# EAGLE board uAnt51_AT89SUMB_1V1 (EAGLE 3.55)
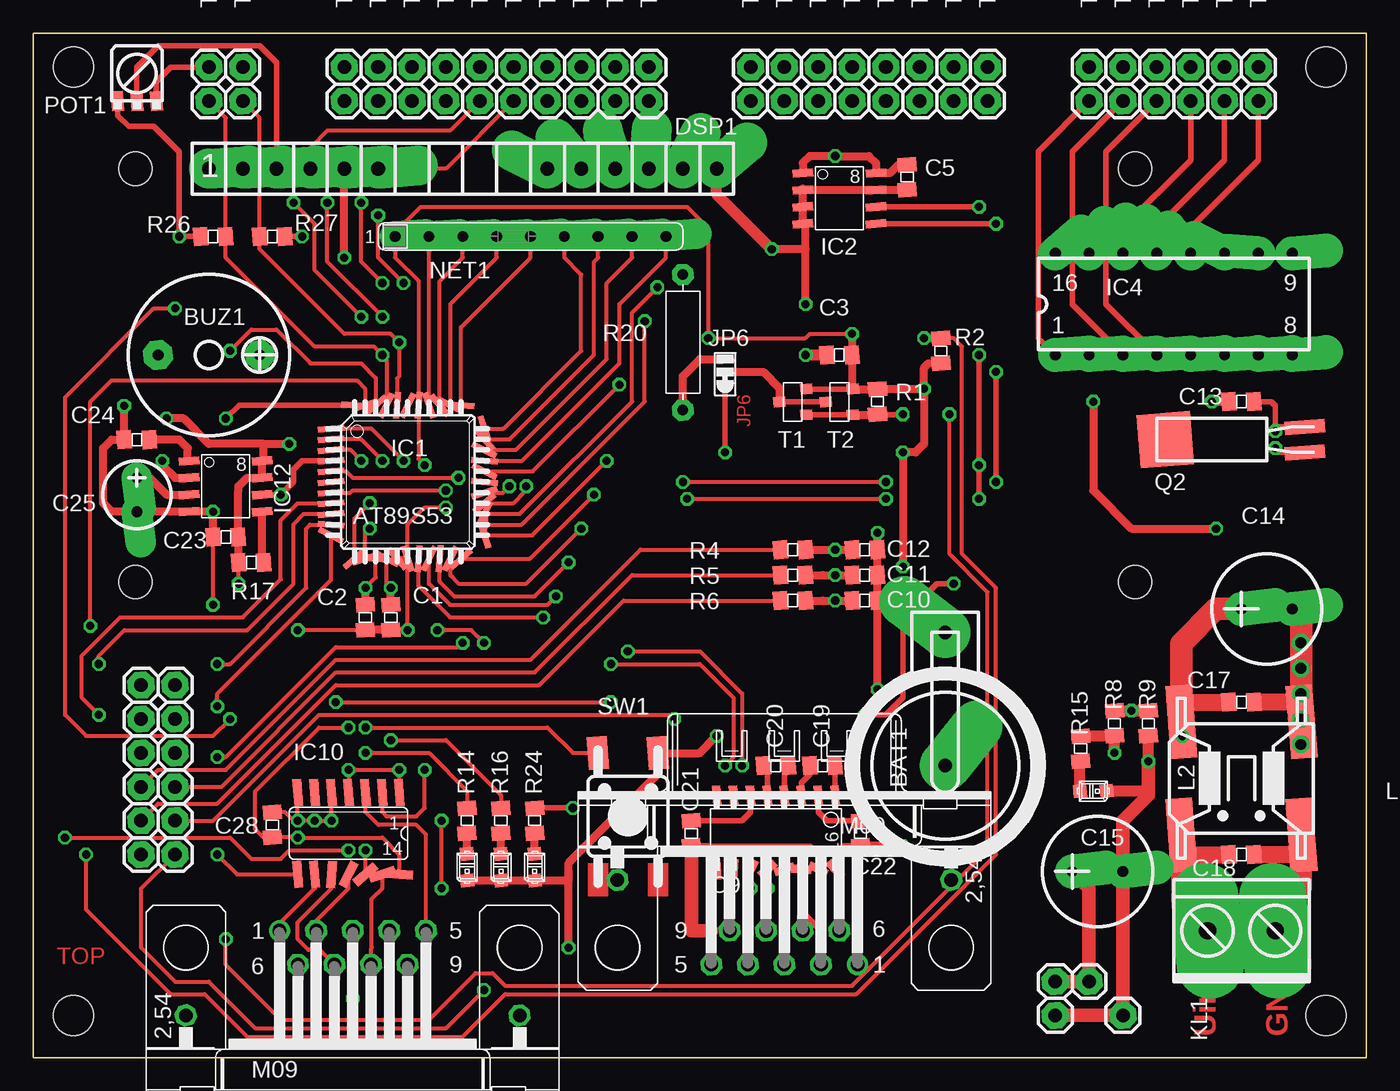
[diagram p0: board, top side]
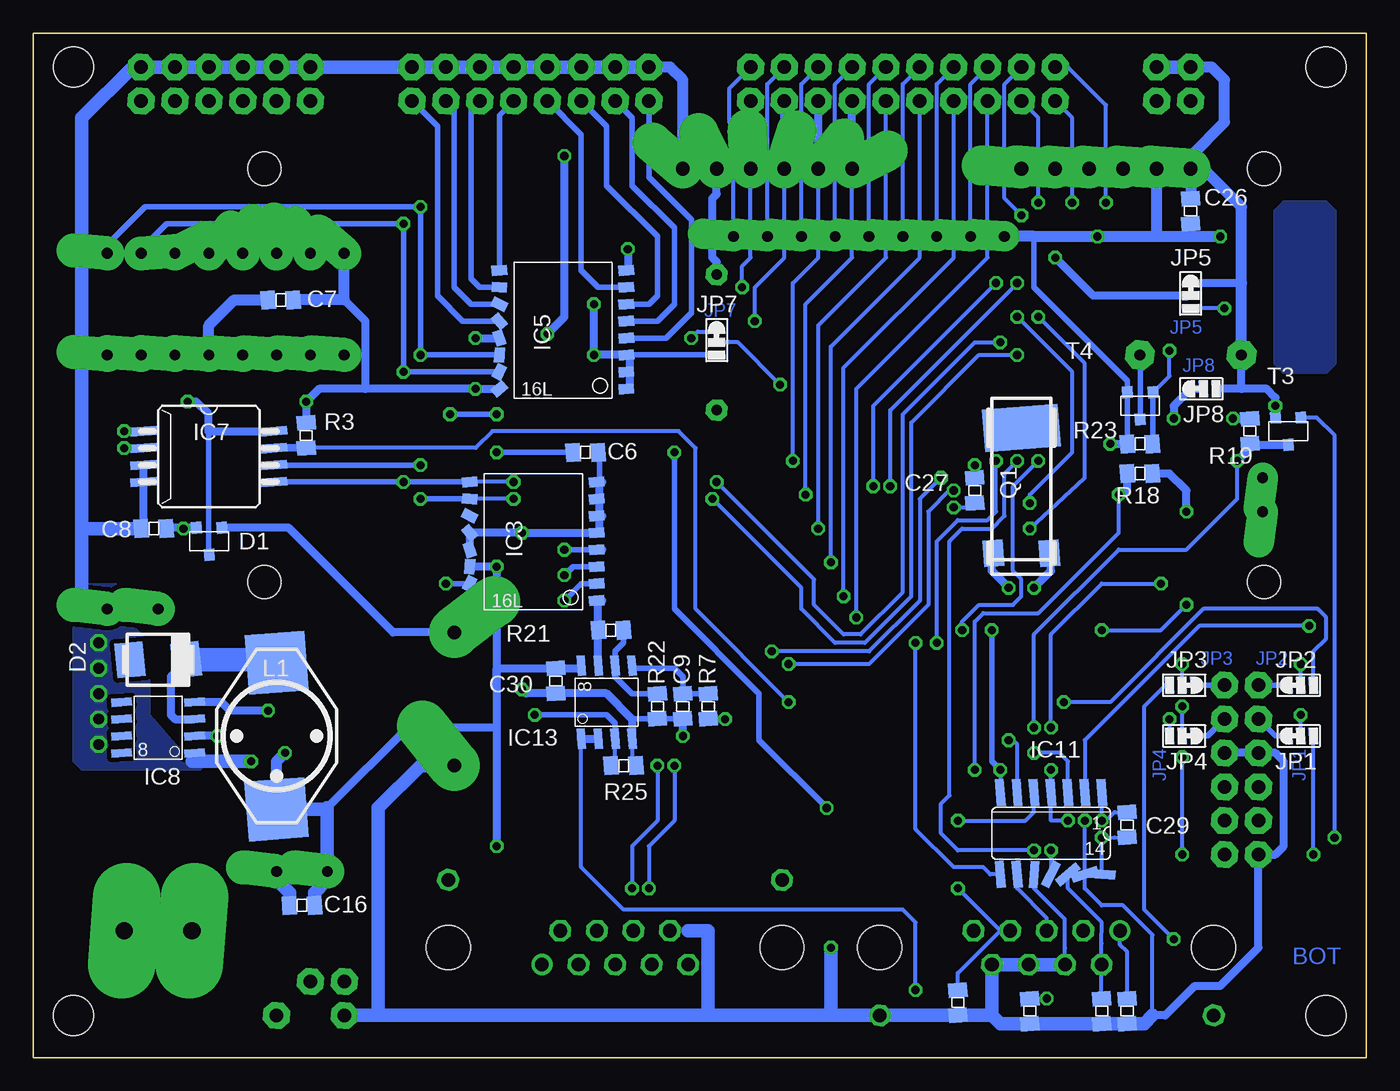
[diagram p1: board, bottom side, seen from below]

Size 100 x 76.81 mm. Coordinates in mm from the lower left corner, seen from the top.
Outline: 0,76.81 0,0 100,0 100,76.81 0,76.81
Copper layers used: Top, Bottom
Holes 3 mm at 96.99,3.16 3.01,3.16 3.01,74.28 96.99,74.28

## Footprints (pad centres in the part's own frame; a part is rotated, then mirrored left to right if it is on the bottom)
YST50X = drill 1.016 pad 3.81 offset: TT 10,0;  0,0
UCW06 = drill 0.813 pad 2.184 octagon:  0,-3.81;  0,3.81
05 = smd 1.092 x 1.397 rotated 4.4:  0.94,0 | smd 1.092 x 1.397 rotated 4.3:  -0.94,0
KO3_8 = drill 0.813 pad 2.54 offset:  -1.905,0;  1.905,0
KO2_5 = drill 0.813 pad 2.3 offset:  -1.27,0;  1.27,0
9H = drill 1.016 pad 1.6 octagon:  5.486,1.27;  2.743,1.27;  0,1.27;  -2.743,1.27;  4.115,-1.27;  1.372,-1.27;  -1.372,-1.27;  -4.115,-1.27;  12.522,-5.08;  -12.522,-5.08 | drill 1.016 pad 1.6 round:  -5.486,1.27 | hole 3.302: 12.522,0; -12.522,0
T23 = smd 0.787 x 0.889 rotated 4.4:  0.991,1.016 | smd 0.787 x 0.889 rotated 4.3:  -0.94,1.016 | smd 0.787 x 0.889 rotated 4.5:  0.025,-1.016
B = smd 2.1 x 2.6 rotated 6.6:  -2.1,0 | smd 2.1 x 2.6 rotated 5.7:  2.1,0
0524B = drill 1.016 pad 3 offset:  0,0;  2.54,0;  5.08,0;  7.62,0;  10.16,0;  12.7,0;  25.4,0;  27.94,0;  30.48,0;  33.02,0;  35.56,0;  38.1,0 | hole 2.5: -5.5,-31; -5.5,0; 69.5,0; 69.5,-31
FP44 = smd 0.45 x 2 rotated 26.8:  4,-5.75 | smd 0.45 x 2 rotated 4.3:  3.2,-5.75;  -4,-5.75 | smd 0.45 x 2 rotated 5:  2.4,-5.75 | smd 0.45 x 2 rotated 4.9:  1.6,-5.75 | smd 0.45 x 2 rotated 4.8:  0.8,-5.75 | smd 0.45 x 2 rotated 4.7:  0,-5.75;  -0.8,-5.75 | smd 0.45 x 2 rotated 4.6:  -1.6,-5.75 | smd 0.45 x 2 rotated 4.5:  -2.4,-5.76;  -1.6,5.75 | smd 0.45 x 2 rotated 4.4:  -3.2,-5.75 | smd 0.45 x 2 rotated 71.9:  4,5.75 | smd 0.45 x 2 rotated 94.4:  3.2,5.75 | smd 0.45 x 2 rotated 116.9:  2.4,5.75 | smd 0.45 x 2 rotated 139.4:  1.6,5.75 | smd 0.45 x 2 rotated 161.9:  0.8,5.75 | smd 0.45 x 2 rotated 184.4:  0,5.75 | smd 0.45 x 2 rotated 206.9:  -0.8,5.75 | smd 0.45 x 2 rotated 27:  -2.4,5.74 | smd 0.45 x 2 rotated 49.5:  -3.2,5.75 | smd 0.45 x 2 rotated 72:  -4,5.75 | smd 2 x 0.45 rotated 49.3:  5.75,-4 | smd 2 x 0.45 rotated 71.8:  5.75,-3.2 | smd 2 x 0.45 rotated 94.3:  5.75,-2.4 | smd 2 x 0.45 rotated 116.8:  5.75,-1.6 | smd 2 x 0.45 rotated 139.3:  5.75,-0.8 | smd 2 x 0.45 rotated 161.8:  5.75,0 | smd 2 x 0.45 rotated 184.3:  5.75,0.8 | smd 2 x 0.45 rotated 206.8:  5.75,1.6 | smd 2 x 0.45 rotated 4.4:  5.74,2.4 | smd 2 x 0.45 rotated 26.9:  5.75,3.2 | smd 2 x 0.45 rotated 49.4:  5.75,4 | smd 2 x 0.45 rotated 94.6:  -5.75,-4 | smd 2 x 0.45 rotated 72.1:  -5.75,-3.2 | smd 2 x 0.45 rotated 49.6:  -5.75,-2.4 | smd 2 x 0.45 rotated 27.1:  -5.75,-1.6 | smd 2 x 0.45 rotated 4.6:  -5.75,-0.8 | smd 2 x 0.45 rotated 207:  -5.75,0 | smd 2 x 0.45 rotated 184.5:  -5.75,0.8 | smd 2 x 0.45 rotated 162:  -5.75,1.6 | smd 2 x 0.45 rotated 139.5:  -5.76,2.4 | smd 2 x 0.45 rotated 117:  -5.75,3.2 | smd 2 x 0.45 rotated 94.5:  -5.75,4
8 = smd 0.61 x 1.524 rotated 4.3:  -1.905,-2.743 | smd 0.61 x 1.524 rotated 4.9:  -1.905,2.743 | smd 0.61 x 1.524 rotated 4.4:  -0.635,-2.743 | smd 0.61 x 1.524 rotated 4.5:  0.635,-2.743 | smd 0.61 x 1.524 rotated 4.8:  -0.635,2.743 | smd 0.61 x 1.524 rotated 4.7:  0.635,2.743;  1.905,2.743 | smd 0.61 x 1.524 rotated 4.6:  1.905,-2.743
16L = smd 0.762 x 1.143 rotated 4.3:  -4.445,-4.648;  3.175,4.877 | smd 0.762 x 1.143 rotated 4.4:  -3.175,-4.648 | smd 0.762 x 1.143 rotated 4.5:  -1.905,-4.648 | smd 0.762 x 1.143 rotated 4.6:  -0.635,-4.648 | smd 0.762 x 1.143 rotated 4.7:  0.635,-4.648;  1.905,-4.648 | smd 0.762 x 1.143 rotated 4.8:  3.175,-4.648 | smd 0.762 x 1.143 rotated 4.9:  4.445,-4.648 | smd 0.762 x 1.143 rotated 5:  4.445,4.877 | smd 0.762 x 1.143 rotated 26.8:  1.905,4.877 | smd 0.762 x 1.143 rotated 49.3:  0.635,4.877 | smd 0.762 x 1.143 rotated 71.8:  -0.635,4.877 | smd 0.762 x 1.143 rotated 94.3:  -1.905,4.877 | smd 0.762 x 1.143 rotated 116.8:  -3.175,4.877 | smd 0.762 x 1.143 rotated 139.3:  -4.445,4.877
L16 = drill 0.813 pad 2.54 offset:  0,0;  2.54,0;  5.08,0;  7.62,0;  10.16,0;  12.7,0;  15.24,0;  17.78,0;  17.78,7.62;  15.24,7.62;  12.7,7.62;  10.16,7.62;  7.62,7.62;  5.08,7.62;  2.54,7.62;  0,7.62
8L = smd 0.65 x 2 rotated 4.3:  -1.905,-4.877 | smd 0.65 x 2 rotated 4.4:  -0.635,-4.877 | smd 0.65 x 2 rotated 4.5:  0.635,-4.877 | smd 0.65 x 2 rotated 4.6:  1.905,-4.877 | smd 0.65 x 2 rotated 4.7:  1.905,4.877;  0.635,4.877 | smd 0.65 x 2 rotated 4.8:  -0.635,4.877 | smd 0.65 x 2 rotated 4.9:  -1.905,4.877
16 = smd 0.61 x 1.524 rotated 4.3:  -3.81,-2.819;  3.81,2.692 | smd 0.61 x 1.524 rotated 139.3:  -3.81,2.692 | smd 0.61 x 1.524 rotated 4.4:  -2.54,-2.819 | smd 0.61 x 1.524 rotated 4.5:  -1.27,-2.819 | smd 0.61 x 1.524 rotated 116.8:  -2.54,2.692 | smd 0.61 x 1.524 rotated 94.3:  -1.27,2.692 | smd 0.61 x 1.524 rotated 4.6:  0,-2.819 | smd 0.61 x 1.524 rotated 71.8:  0,2.692 | smd 0.61 x 1.524 rotated 4.7:  1.27,-2.819;  2.54,-2.819 | smd 0.61 x 1.524 rotated 49.3:  1.27,2.692 | smd 0.61 x 1.524 rotated 4.8:  3.81,-2.819 | smd 0.61 x 1.524 rotated 26.8:  2.54,2.692 | smd 0.61 x 1.524 rotated 4.9:  5.08,-2.819 | smd 0.61 x 1.524 rotated 5:  5.08,2.692
14 = smd 0.66 x 2.032 rotated 4.3:  -3.81,-3.073;  1.27,3.073 | smd 0.66 x 2.032 rotated 94.3:  -3.81,3.073 | smd 0.66 x 2.032 rotated 4.4:  -2.54,-3.073 | smd 0.66 x 2.032 rotated 4.5:  -1.27,-3.073 | smd 0.66 x 2.032 rotated 71.8:  -2.54,3.073 | smd 0.66 x 2.032 rotated 49.3:  -1.27,3.073 | smd 0.66 x 2.032 rotated 4.6:  0,-3.073 | smd 0.66 x 2.032 rotated 26.8:  0,3.073 | smd 0.66 x 2.032 rotated 4.7:  1.27,-3.073;  2.54,-3.073 | smd 0.66 x 2.032 rotated 5:  2.54,3.073 | smd 0.66 x 2.032 rotated 4.8:  3.81,-3.073 | smd 0.66 x 2.032 rotated 4.9:  3.81,3.073
3S = smd 0.635 x 1.27 rotated 4.4:  0,0 | smd 0.635 x 1.27 rotated 4.5:  0.953,0 | smd 0.317 x 1.27 rotated 4.3:  -0.794,0
2 = drill 1.3 pad 5.08 long:  0,2.54;  0,-2.54
3316 = smd 4.5 x 4.5 rotated 4.4:  5.5,0 | smd 4.5 x 4.5 rotated 4.3:  -5.5,0
-2S = smd 5.5 x 2 rotated 4.4:  -4.25,4.5 | smd 5.5 x 2 rotated 4.5:  -4.25,-4.5 | smd 5.5 x 2 rotated 4.6:  4.25,-4.5 | smd 5.5 x 2 rotated 4.3:  4.25,4.5
M676 = smd 1 x 1 rotated 5.7:  0,1 | smd 1 x 1 rotated 6.6:  0,-1
L9 = drill 0.813 pad 2.3 offset:  0,0;  2.54,0;  5.08,0;  7.62,0;  10.16,0;  12.7,0;  15.24,0;  17.78,0;  20.32,0
PC25 = smd 0.9 x 1.5 rotated 4.4:  0,0 | smd 0.9 x 1.5 rotated 4.3:  -1.45,0 | smd 0.9 x 1.5 rotated 4.5:  1.45,0
SMXSMD = smd 2 x 1.5 rotated 4.3:  -4.7,2.1 | smd 2 x 1.5 rotated 4.4:  -4.7,-2.1 | smd 3.2 x 5.7 rotated 4.5:  4.7,0
ARZRTC = smd 3 x 1 rotated 4.3:  -6.985,0.953 | smd 3 x 1 rotated 4.4:  -6.985,-0.953 | smd 4 x 4 rotated 4.5:  3.493,0
10 = drill 0.813 pad 1.6 octagon:  -5.08,0;  5.08,0
01XX = smd 2.5 x 1.5 rotated 4.4:  -4.75,-2.25 | smd 2.5 x 1.5 rotated 4.3:  -4.75,2.25
D = drill 1.016 pad 2 octagon:  0,0

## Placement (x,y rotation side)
BAT1  CR1216  [YST50X]  68.41,21.89 90 top
BUZ1  F_UCW06  [UCW06]  13.17,52.69 270 top
C1  33pF  [05]  26.82,33 90 top
C2  33pF  [05]  24.92,33 90 top
C3  100nF  [05]  60.48,52.69 180 top
C5  100nF  [05]  65.56,66.03 270 top
C6  100nF  [05]  58.57,45.39 0 bottom
C7  100nF  [05]  81.43,56.82 180 bottom
C8  100nF  [05]  90.96,39.67 180 bottom
C9  100nF  [05]  51.27,26.34 90 bottom
C10  100nF  [05]  62.38,34.27 180 top
C11  100nF  [05]  62.38,36.18 180 top
C12  100nF  [05]  62.38,38.09 180 top
C13  22pF  [05]  90.64,49.2 180 top
C14  100æF/35V  [KO3_8]  92.55,33.64 0 top
C15  470æF/10V  [KO3_8]  79.84,13.96 0 top
C16  100nF  [05]  79.84,11.41 0 bottom
C17  100nF  [05]  90.64,26.66 180 top
C18  100nF  [05]  90.64,15.22 180 top
C19  100nF  [05]  59.21,21.89 0 top
C20  100nF  [05]  55.71,21.89 0 top
C21  100nF  [05]  49.37,16.81 90 top
C22  100nF  [05]  62.06,16.81 270 top
C23  100nF  [05]  14.44,39.04 180 top
C24  100nF  [05]  7.77,46.34 0 top
C25  22æF  [KO2_5]  7.77,42.21 270 top
C26  100nF  [05]  13.17,63.48 90 bottom
C27  100nF  [05]  29.36,42.53 270 bottom
C28  100nF  [05]  17.93,17.45 270 top
C29  100nF  [05]  17.93,17.45 270 bottom
C30  100nF  [05]  60.8,28.24 90 bottom
CON1  SPI/PROG (M)  [9H]  23.96,8.24 0 top
CON2  V.24 (F)  [9H]  56.35,8.24 180 top
D1  BAT54C  [T23]  86.83,38.72 0 bottom
D2  10BQ100  [B]  90.64,29.83 180 bottom
DSP1  MC-162-2  [0524B]  13.17,66.66 0 top
IC1  AT89S53  [FP44]  28.09,43.16 270 top
IC2  M24C02  [8]  60.48,64.44 270 top
IC3  PCF8591T  [16L]  62.38,38.72 90 bottom
IC4  DS1803-xx  [L16]  76.67,52.69 0 top
IC5  PCF8574T  [16L]  60.16,54.59 90 bottom
IC7  PCF8583T  [8L]  86.83,45.07 270 bottom
IC8  MIC4680  [8]  90.64,24.75 90 bottom
IC9  MAX202CSE  [16]  56.35,16.81 180 top
IC10  74HC125  [14]  23.65,16.81 180 top
IC11  74HC125  [14]  23.65,16.81 180 bottom
IC12  TL7705AxD  [8]  14.44,42.85 270 top
IC13  LMV358M  [8]  56.98,26.66 0 bottom
JP1  JP3  [3S]  4.92,24.12 0 bottom
JP2  JP3  [3S]  4.92,27.93 0 bottom
JP3  JP3  [3S]  13.81,27.93 180 bottom
JP4  JP3  [3S]  13.81,24.12 180 bottom
JP5  JP3  [3S]  13.17,57.13 270 bottom
JP6  JP3  [3S]  51.91,51.42 90 top
JP7  JP3  [3S]  48.73,53.64 270 bottom
JP8  JP3  [3S]  12.22,50.15 0 bottom
KL1  [2]  90.64,9.51 90 top
L1  68æH  [3316]  81.75,24.12 270 bottom
L2  DKFS-6248-02D5  [-2S]  90.64,20.94 90 top
LED1  LBM676 bl  [M676]  32.54,14.27 0 top
LED2  LGM670 gn  [M676]  79.53,19.99 90 top
LED3  LSM676 rt  [M676]  35.08,14.27 0 top
LED4  LYM676 ge  [M676]  37.62,14.27 0 top
NET1  3k3 (opt.)  [L9]  27.14,61.58 0 top
POT1  5k  [PC25]  7.77,71.74 0 top
Q1  24MHz  [SMXSMD]  25.87,42.53 90 bottom
Q2  32.768kHz  [ARZRTC]  88.42,46.34 180 top
R1  1M  [05]  63.34,49.2 90 top
R2  10k  [05]  68.1,53.01 270 top
R3  10k  [05]  79.53,46.66 90 bottom
R4  47k  [05]  56.98,38.09 180 top
R5  47k  [05]  56.98,36.18 180 top
R6  47k  [05]  56.98,34.27 180 top
R7  47k  [05]  49.37,26.34 270 bottom
R8  4k7*  [05]  81.11,25.07 270 top
R9  1k5*  [05]  83.66,25.07 90 top
R10  1k  [05]  19.84,3.48 270 bottom
R11  1k  [05]  17.93,3.48 270 bottom
R12  1k  [05]  25.23,3.48 270 bottom
R13  1k  [05]  30.63,4.11 270 bottom
R14  680R  [05]  32.54,17.77 90 top
R15  680R  [05]  78.58,23.16 90 top
R16  680R  [05]  35.08,17.77 90 top
R17  10k  [05]  16.34,37.13 180 top
R18  10k  [05]  16.98,43.8 180 bottom
R19  10k  [05]  8.73,46.97 90 bottom
R20  68R  [10]  48.73,53.64 90 top
R21  0R  [05]  56.67,32.05 0 bottom
R22  xxR (opt.)  [05]  53.17,26.34 90 bottom
R23  1M  [05]  16.98,46.02 180 bottom
R24  680R  [05]  37.62,17.77 90 top
R25  10k  [05]  55.71,21.89 180 bottom
R26  4k7  [05]  13.49,61.58 180 top
R27  4k7  [05]  17.93,61.58 0 top
SW1  RESET  [01XX]  44.6,18.08 270 top
T1  TP0202T  [T23]  56.98,49.2 270 top
T2  TP0202T  [T23]  60.48,49.2 270 top
T3  BC846  [T23]  5.87,46.97 0 bottom
T4  TP0202T  [T23]  16.98,48.88 0 bottom
TP1  AD0/P00  [D]  28.41,74.28 90 top
TP2  AD1/P01  [D]  30.95,74.28 90 top
TP3  AD2/P02  [D]  33.49,74.28 90 top
TP4  AD3/P03  [D]  36.03,74.28 90 top
TP5  AD4/P04  [D]  38.57,74.28 90 top
TP6  AD5/P05  [D]  41.11,74.28 90 top
TP7  AD6/P06  [D]  43.65,74.28 90 top
TP8  AD7/P07  [D]  46.19,74.28 90 top
TP9  A8 /P20  [D]  28.41,71.74 90 top
TP10  A9 /P21  [D]  30.95,71.74 90 top
TP11  A10/P22  [D]  33.49,71.74 90 top
TP12  A11/P23  [D]  36.03,71.74 90 top
TP13  A12/P24  [D]  38.57,71.74 0 top
TP14  A13/P25  [D]  41.11,71.74 0 top
TP15  A14/P26  [D]  43.65,71.74 0 top
TP16  A15/P27  [D]  46.19,71.74 0 top
TP17  RD#/P37  [D]  23.33,74.28 90 top
TP18  WR#/P36  [D]  23.33,71.74 90 top
TP19  ALE  [D]  25.87,71.74 90 top
TP20  PSEN#  [D]  25.87,74.28 90 top
TP21  INT0#  [D]  8.09,25.39 0 top
TP22  INT1#  [D]  8.09,27.93 0 top
TP23  T0  [D]  10.63,27.93 0 top
TP24  T1  [D]  10.63,25.39 0 top
TP25  GND  [D]  8.09,22.85 0 top
TP26  AI0  [D]  10.63,17.77 0 top
TP27  AI1  [D]  8.09,17.77 0 top
TP28  AI2  [D]  10.63,20.3 0 top
TP29  AI3  [D]  8.09,20.3 0 top
TP30  GND  [D]  10.63,22.85 0 top
TP31  AO  [D]  10.63,15.22 0 top
TP32  GND  [D]  8.09,15.22 0 top
TP33  XIO0  [D]  53.81,71.74 90 top
TP34  XIO1  [D]  56.35,71.74 90 top
TP35  XIO2  [D]  58.89,71.74 90 top
TP36  XIO3  [D]  61.43,71.74 90 top
TP37  XIO4  [D]  63.97,71.74 90 top
TP38  XIO5  [D]  66.51,71.74 90 top
TP39  XIO6  [D]  69.05,71.74 90 top
TP40  XIO7  [D]  71.59,71.74 90 top
TP41  GND  [D]  71.59,74.28 90 top
TP42  GND  [D]  69.05,74.28 90 top
TP43  GND  [D]  66.51,74.28 90 top
TP44  GND  [D]  63.97,74.28 90 top
TP45  GND  [D]  61.43,74.28 90 top
TP46  GND  [D]  58.89,74.28 90 top
TP47  GND  [D]  56.35,74.28 90 top
TP48  GND  [D]  53.81,74.28 90 top
TP49  RL0  [D]  89.37,71.74 90 top
TP50  RW0  [D]  91.91,71.74 90 top
TP51  RH0  [D]  86.83,71.74 90 top
TP52  RL1  [D]  81.75,71.74 90 top
TP53  RW1  [D]  84.29,71.74 90 top
TP54  RH1  [D]  79.21,71.74 90 top
TP55  GND  [D]  79.21,74.28 90 top
TP56  GND  [D]  81.75,74.28 90 top
TP57  GND  [D]  84.29,74.28 90 top
TP58  GND  [D]  86.83,74.28 90 top
TP59  GND  [D]  89.37,74.28 90 top
TP60  GND  [D]  91.91,74.28 90 top
TP61  SCL  [D]  13.17,71.74 90 top
TP62  SDA  [D]  15.71,71.74 90 top
TP63  GND  [D]  13.17,74.28 90 top
TP64  GND  [D]  15.71,74.28 90 top
TP65  +5V  [D]  76.67,5.7 0 top
TP66  +5V  [D]  79.21,5.7 0 top
TP67  GND  [D]  81.75,3.16 0 top
TP68  GND  [D]  76.67,3.16 0 top

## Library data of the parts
BAT1 BUZ1 C1-C3 C5-C30 D1 D2 DSP1 IC1-IC5 IC7-IC9 IC12 IC13 JP1-JP8 KL1 L1 L2 LED1-LED4 NET1 POT1 Q1 Q2 R1-R19 R21-R27 SW1 T1-T4 TP1-TP68 = Custom
CON1 CON2 = SUBD-A
IC10 IC11 = 74XXSMD
R20 = DISCRETE

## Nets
+5V: C3. C5. C6. C7. C8. C15. C16. C22. C23. C26. C27. C28. C29. C30. D1. DSP1. IC1. IC2. IC3. IC4. IC5. IC9. IC10. IC11. IC12. IC13. JP7. L1. NET1. POT1. R1. R2. R3. R8. R15. R17. R19. R23. R26. R27. T1. T2. T4. TP65. TP66.
/BL: JP3. R1. T1. T2.
/RD: IC1. TP17.
/SS: IC1. JP8.
/WR: IC1. TP18.
A8: IC1. TP9.
A9: IC1. TP10.
A10: DSP1. IC1. TP11.
A11: DSP1. IC1. TP12.
A12: DSP1. IC1. TP13.
A13: DSP1. IC1. TP14.
A14: DSP1. IC1. TP15.
A15: DSP1. IC1. TP16.
AD0: IC1. NET1. TP1.
AD1: IC1. NET1. TP2.
AD2: IC1. NET1. TP3.
AD3: IC1. NET1. TP4.
AD4: IC1. NET1. TP5.
AD5: IC1. NET1. TP6.
AD6: IC1. NET1. TP7.
AD7: IC1. NET1. TP8.
AIN0: IC3. IC13. R21.
AIN1: C10. IC3. R6.
AIN2: C11. IC3. R5.
AIN3: C12. IC3. R4.
ALE: IC1. TP19.
AOUT: IC3. IC13. R25.
BEEPER: IC1. R23. T4.
GND: BAT1. BUZ1. C1. C2. C3. C5. C6. C7. C8. C9. C10. C11. C12. C14. C15. C16. C17. C21. C23. C24. C25. C26. C27. C28. C29. C30. CON1. CON2. D2. DSP1. IC1. IC2. IC3. IC4. IC5. IC7. IC8. IC9. IC10. IC11. IC12. IC13. JP5. JP7. JP8. L2. LED1. LED2. LED3. LED4. POT1. R9. R10. R11. R12. R13. R18. R22. R25. SW1. T3. TP25. TP30. TP32. TP41. TP42. TP43. TP44. TP45. TP46. TP47. TP48. TP55. TP56. TP57. TP58. TP59. TP60. TP63. TP64. TP67. TP68.
INTRTC: IC7. JP2. R3.
INTXIO: IC5. JP1. R2.
LCDRW: JP4. JP5.
LED0: IC1. IC11.
LED+: JP6. R20.
MISO: IC1. IC10.
MOSI: IC1. IC10.
N$1: DSP1. POT1.
N$2: JP6. T1. T2.
N$3: DSP1. R20.
N$4: C2. IC1. Q1.
N$5: C1. IC1. Q1.
N$6: C13. D1. IC7.
N$7: IC5. TP40.
N$8: IC5. TP39.
N$9: IC5. TP38.
N$10: IC5. TP37.
N$11: IC5. TP36.
N$12: IC5. TP35.
N$13: IC5. TP34.
N$14: IC5. TP33.
N$23: C13. IC7. Q2.
N$24: D2. IC8. L1.
N$25: C14. C17. IC8. L2.
N$26: CON1. IC11. R10.
N$27: IC11. R14.
N$28: C18. KL1. L2.
N$29: C18. KL1. L2.
N$30: IC8. R8. R9.
N$31: IC4. TP54.
N$32: IC4. TP53.
N$33: IC4. TP52.
N$34: IC4. TP51.
N$35: IC4. TP50.
N$36: IC4. TP49.
N$37: CON1. IC10.
N$38: CON1. IC11. R12.
N$40: LED3. R16.
N$41: IC11. R16.
N$42: CON1. IC10. R11.
N$43: CON2. IC9.
N$44: CON2. IC9.
N$45: C25. IC12.
N$46: CON1. IC11. R13.
N$47: CON1. IC10.
N$48: LED1. R14.
N$49: LED2. R15.
N$50: C20. IC9.
N$51: C20. IC9.
N$52: C19. IC9.
N$53: C19. IC9.
N$54: IC12. R19. SW1. T3.
N$55: IC12. R17.
N$57: R4. TP29.
N$58: R5. TP28.
N$59: R6. TP27.
N$60: R7. TP26.
N$61: IC1. JP4.
N$62: JP4. TP24.
N$63: C24. IC12.
N$64: IC1. JP3.
N$65: JP3. TP23.
N$66: IC1. JP2.
N$67: IC1. JP1.
N$68: JP2. TP22.
N$69: JP1. TP21.
N$70: DSP1. JP5.
N$71: IC13. R21. R22.
N$72: IC1. JP7.
N$73: IC7. Q2.
N$74: BUZ1. T4.
N$75: IC13. TP31.
N$77: JP6. R24.
N$78: LED4. R24.
N$79: C9. IC13. R7.
PROG: IC11. T3.
PSEN: IC1. TP20.
RSTO: IC1. IC10. IC12. R18.
RXD: IC1. IC9.
SCK: IC1. IC11.
SCL: IC1. IC2. IC3. IC4. IC5. IC7. R26. TP61.
SDA: IC1. IC2. IC3. IC4. IC5. IC7. R27. TP62.
TXD: IC1. IC9.
UBATT: BAT1.TT D1.
V+: C22. IC9.
V-: C21. IC9.

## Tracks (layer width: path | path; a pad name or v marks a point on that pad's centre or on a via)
+5V  (via drill 0.61 pad 1.02)
  Top 0.305: IC11. 27.46,15.22 26.19,16.5 v19.84,16.5 19.82,16.51 17.93,16.51 17.93,16.5 17.3,16.5 16.66,17.13 16.66,19.99 21.42,24.75 v23.65,24.75 | v61.43,54.28 58.25,54.28 57.94,53.96 v50.63,53.96 50.63,62.21 49.05,63.8 29.04,63.8 27.14,61.9 27.14,61.58 27.14,59.99 28.89,58.24 28.89,48.91 28.89,44.9 v29.36,44.43 | 15.41,37.13 15.41,35.56 v15.39,35.54
  Top 0.406: 6.32,71.74 6.32,70.65 7.14,69.84 9.04,69.84 10.95,67.93 v10.95,61.58 12.55,61.58 | 61.42,50.14 58,50.14 | 62.06,15.87 60.81,15.87 60.16,15.22 60.16,14.12 60.16,13.96 | v20.15,61.58 18.87,61.58
  Top 0.61: 61.44,50.14 61.49,50.14 63.32,50.14 63.34,50.15 | 61.43,50.15 61.42,50.14 | 63.34,50.15 63.34,50.14 61.44,50.14 | 61.43,50.15 61.44,50.14 | C3. 61.43,50.15 | 63.34,50.15 v66.83,50.15 | 63.22,66.34 63.22,67.09 62.7,67.61 v60.16,67.61 58.25,67.61 57.73,67.09 57.73,66.34 | C3. 61.42,54.27 v61.43,54.28 | C5. 64.91,66.97 64.29,66.34 63.22,66.34 | 63.22,66.34 63.02,66.34 | 17.3,44.75 17.18,44.75 | 17.3,44.75 17.18,44.64 17.18,43.48 16.03,43.48 15.39,42.85 15.39,42.53 15.38,42.52 C23. 15.39,39.04 15.41,39.02 15.41,37.13 | v10,47.93 11.27,47.93 13.17,46.02 17.3,46.02 | 17.3,46.02 v19.2,46.02 | 17.3,44.75 17.3,46.02 | 57.94,50.15 57.95,50.14 58,50.14 | 62.06,15.87 63.96,15.87 v65.24,15.86 | v79.53,49.2 79.53,42.53 82.39,39.67 v88.73,39.67 | v66.83,50.15 66.83,46.02 66.19,45.39 v65.24,45.39 v65.24,36.81 | v66.83,50.15 66.83,51.74 67.14,52.05 68.1,52.05 68.1,52.07
  Top 0.813: v81.11,22.85 81.11,24.12 | C3. | 81.11,24.12 81.11,24.13 | 78.58,24.1 81.1,24.1 81.11,24.12
  Top 1.016: 77.94,13.96 79.21,12.68 TP66. TP65.
  Bottom 0.305: v19.84,16.5 IC10. v19.84,16.5 | 17.93,16.51 18.88,16.5 19.51,16.51 19.82,16.51 v19.84,16.5 | v29.36,44.43 C27. | JP7. 50.16,54.44 v50.63,53.96 | v15.39,35.54 19.84,35.54 23.65,31.73 v23.65,24.75
  Bottom 0.406: 17.93,46.02 17.92,46.02 | 17.92,46.03 17.92,49.9 17.92,50.77 24.92,57.77 24.92,61.58 | v65.24,45.39 C6.
  Bottom 0.61: IC5. v66.83,50.15 75.08,50.15 | 65.24,24.75 71.91,24.75 77.94,18.72 | v60.16,67.61 60.16,55.55 v61.43,54.28 | 8.73,47.91 9.98,47.91 v10,47.93 | 17.92,46.03 17.93,46.02 v19.2,46.02 | 76.67,56.82 75.08,55.23 75.08,50.15 | C8. 89.69,39.67 89.62,39.74 87.77,39.74 87.77,39.68 87.78,39.67 v88.73,39.67 | 65.24,24.75 v65.24,15.86 | 75.08,50.15 78.58,50.15 v79.53,49.2 79.53,47.6 | 65.24,34.27 65.24,27.61 | 65.24,34.27 IC3. | 65.24,34.27 v65.24,36.81 67.26,36.81 | 65.24,27.61 65.23,29.18 60.8,29.18 60.8,29.2 58.89,29.2 58.89,29.4 | 65.24,27.61 65.24,24.75
  Bottom 0.813: v81.11,22.85 81.75,22.21 81.75,18.62 | 15.71,61.58 v20.15,61.58 24.92,61.58 27.14,61.58 | 15.71,61.58 15.71,66.66 | 13.17,61.58 v10.95,61.58 | 13.17,61.58 C26. | 15.71,61.58 13.17,61.58 | C7. 76.67,56.82 IC4.
  Bottom 1.016: 78.91,11.41 78.91,12.35 77.94,13.32 77.94,13.96 77.94,18.62 | 77.94,18.62 81.75,18.62 | 77.94,18.72 77.94,18.62
/BL  (via drill 0.61 pad 1.02)
  Top 0.305: v68.73,48.24 68.73,37.77 71.59,34.91 71.59,15.54 61.43,5.38 35.39,5.38 34.44,6.33 33.17,6.33 29.68,2.84 18.57,2.84 14.44,6.97 v14.44,8.88
  Top 0.406: 61.49,48.21 61.47,48.21 61.43,48.24 61.39,48.21 58,48.21 65.2,48.21 v65.24,48.24
  Top 0.61: R1. 63.34,48.24 63.3,48.21 61.49,48.21
  Bottom 0.305: 14.76,27.93 15.08,27.93 16.66,26.34 16.66,11.1 v14.44,8.88
  Bottom 0.406: v68.73,48.24 v65.24,48.24
/RD  (via drill 0.61 pad 1.02)
  Top 0.305: 24.89,37.41 24.89,39.33 v25.23,39.67 | v19.52,64.12 21.11,62.53 21.11,59.04 v24.6,55.55
  Bottom 0.305: TP17. 22.38,74.28 19.52,71.42 v19.52,64.12 | v25.23,39.67 21.11,43.48 21.11,52.05 v24.6,55.55
/SS  (via drill 0.61 pad 1.02)
  Top 0.406: 24.09,48.91 15.43,48.91 v14.44,47.93
  Bottom 0.61: 12.22,50.15 JP8. 13.17,50.15 14.44,48.88 v14.44,47.93
/WR  (via drill 0.61 pad 1.02)
  Top 0.305: 24.09,37.41 24.09,40.43 v25.23,41.58 | v22.06,64.12 22.06,59.67 v26.19,55.55
  Bottom 0.305: TP18. 22.06,70.47 v22.06,64.12 | v25.23,41.58 25.23,42.21 22.06,45.39 22.06,51.42 v26.19,55.55
A8  (via drill 0.61 pad 1.02)
  Top 0.305: 28.89,37.41 28.89,35.38 31.27,33 v38.25,33
  Bottom 0.305: TP9. 28.41,59.99 38.25,50.15 v38.25,33
A9  (via drill 0.61 pad 1.02)
  Top 0.305: 29.69,37.41 29.69,35.53 31.27,33.96 38.57,33.96 v39.2,34.59
  Bottom 0.305: TP10. 30.95,59.99 39.2,51.74 v39.2,34.59
A10  (via drill 0.61 pad 1.02)
  Top 0.305: 20.79,66.66 20.79,68.25 22.06,69.52 31.27,69.52 TP11. | 30.49,37.42 30.49,35.68 31.58,34.59 37.62,34.59 v40.16,37.13
  Bottom 0.305: TP11. 33.49,59.99 40.16,53.32 v40.16,37.13
A11  (via drill 0.61 pad 1.02)
  Top 0.305: 25.87,66.66 30.95,66.66 TP12. | 31.29,37.41 31.29,36.15 31.9,35.54 36.98,35.54 v41.11,39.67
  Bottom 0.305: TP12. 36.03,59.99 41.11,54.91 v41.11,39.67
A12  (via drill 0.61 pad 1.02)
  Top 0.305: 32.09,37.41 37.27,37.41 v42.06,42.21
  Bottom 0.305: v42.06,42.21 42.06,56.5 38.57,59.99 38.57,66.66
  Bottom 0.61: 38.57,72.06 TP13. 38.57,66.66
A13  (via drill 0.61 pad 1.02)
  Top 0.305: 33.84,39.16 37.43,39.16 v43.02,44.75
  Bottom 0.305: v43.02,44.75 43.02,58.09 41.11,59.99 41.11,66.66
  Bottom 0.61: 41.11,66.66 TP14.
A14  (via drill 0.61 pad 1.02)
  Top 0.305: 33.84,39.96 36.64,39.96 45.87,49.2 v45.87,55.23
  Bottom 0.305: v45.87,55.23 45.87,57.77 43.65,59.99 43.65,66.66
  Bottom 0.61: 43.65,66.66 TP15.
A15  (via drill 0.61 pad 1.02)
  Top 0.305: 33.84,40.77 36.49,40.77 44.92,49.2 44.92,55.86 v46.82,57.77
  Bottom 0.305: v46.82,57.77 46.82,59.36 46.19,59.99 46.19,66.66
  Bottom 0.61: 46.19,66.66 TP16.
AD0
  Top 0.305: 29.68,61.58 29.68,55.55 29.69,53.63 29.69,48.91
  Bottom 0.305: 29.68,61.58 29.68,73.01 TP1.
AD1
  Top 0.305: 30.49,48.92 30.49,58.23 32.22,59.99 32.22,61.58
  Bottom 0.305: 32.22,61.58 32.22,73.01 TP2.
AD2
  Top 0.305: 31.29,48.91 31.29,56.52 34.76,59.99 34.76,61.58
  Bottom 0.305: 34.76,61.58 34.76,73.01 TP3.
AD3
  Top 0.305: IC1. 32.09,54.78 37.3,59.99 37.3,61.58
  Bottom 0.305: 37.3,61.58 37.3,73.01 TP4.
AD4
  Top 0.305: 33.84,47.16 35.27,47.16 41.11,53.01 41.11,58.72 39.84,59.99 39.84,61.58
  Bottom 0.305: 39.84,61.58 39.84,73.01 TP5.
AD5
  Top 0.305: 33.84,46.36 35.74,46.36 42.06,52.69 42.06,59.67 42.38,59.99 42.38,61.58
  Bottom 0.305: 42.38,61.58 42.38,73.01 TP6.
AD6
  Top 0.305: 33.83,45.56 36.21,45.56 43.02,52.37 43.02,58.09 44.92,59.99 44.92,61.58
  Bottom 0.305: 44.92,61.58 44.92,73.01 TP7.
AD7
  Top 0.305: 33.84,44.77 36.68,44.77 43.97,52.05 43.97,56.5 47.46,59.99 NET1.
  Bottom 0.305: NET1. 47.46,69.84 47.78,70.15 47.78,72.69 TP8.
AIN0
  Bottom 0.61: 57.3,34.27 57.51,34.27 57.62,34.27 57.62,31.73 | 57.62,31.73 R21. | 57.62,29.4 57.62,31.73
AIN1  (via drill 0.61 pad 1.02)
  Top 0.61: 59.21,34.27 61.44,34.27 | 59.21,34.27 v60.16,34.27 | R6. 59.21,34.27
  Bottom 0.406: 57.51,35.54 58.89,35.54 v60.16,34.27
AIN2  (via drill 0.61 pad 1.02)
  Top 0.61: 59.21,36.18 61.44,36.18 | 59.21,36.18 v60.16,36.18 | R5. 59.21,36.18
  Bottom 0.406: v60.16,36.18 59.52,36.81 57.51,36.81
AIN3  (via drill 0.61 pad 1.02)
  Top 0.61: 61.44,38.09 v60.16,38.09 R4.
  Bottom 0.406: v60.16,38.09 57.51,38.09
  Bottom 0.61: 57.51,38.09 57.3,38.09
ALE  (via drill 0.61 pad 1.02)
  Top 0.305: v24.6,64.12 24.6,59.67 v26.19,58.09 | 33.84,42.36 35.23,42.36 v35.71,42.85
  Bottom 0.305: TP19. 24.6,70.47 v24.6,64.12 | v35.71,42.85 35.71,48.56 v26.19,58.09
AOUT  (via drill 0.61 pad 1.02)
  Top 0.406: v62.38,25.7 63.97,25.7 65.24,26.97 65.24,33 67.78,35.54 v69.05,35.54
  Bottom 0.305: 56.67,21.89 56.66,21.89 56.35,21.89 56.35,23.91
  Bottom 0.406: 56.35,23.91 56.35,25.07 56.98,25.7 v62.38,25.7 | v69.05,35.54 67.26,35.54
BEEPER  (via drill 0.61 pad 1.02)
  Top 0.305: 25.69,48.91 25.69,50.96 24.6,52.05 20.79,52.05 18.25,54.59 16.34,54.59 v14.76,53.01
  Bottom 0.305: 15.99,49.87 16.03,49.83 | 15.99,49.9 15.99,49.87 | v14.76,53.01 14.76,51.1 15.99,49.87
  Bottom 0.406: 15.99,49.9 15.99,46.06 16.03,46.02
  Bottom 0.61: R23. 16.03,46.02
GND  (via drill 0.61 pad 1.02, 0.81 pad 1.27)
  Top 0.305: 27.79,32.06 C1. | v28.09,32.05 27.79,32.06 | v28.09,32.05 28.09,37.45 28.09,39.99 29.36,41.26 v30.95,41.26 | C28. 18.88,18.4 19.52,17.77 v19.84,17.77 | v19.84,17.77 19.84,19.89 | v19.84,17.77 v21.11,17.77 v22.38,17.77 22.38,19.89 | 22.38,13.74 22.38,12.68 19.84,10.14 19.84,8.88 20.63,8.08 21.48,8.08 22.59,6.97 | 26.19,13.74 26.19,12.68 25.39,11.89 25.39,8.24 25.34,8.14 25.34,6.97 | 19.84,19.89 19.84,19.99 | v19.84,17.77 19.84,19.89 | 23.65,19.89 v23.65,21.57 v27.46,21.57 27.46,19.89 | 27.79,32.06 28.09,32.06 v28.09,32.05 | v19.84,17.77 19.84,19.89 | 13.5,39.04 13.49,39.02 v13.49,33.96 | C2. 24.92,32.05 v19.84,32.05
  Top 0.406: 28.09,37.41 28.09,37.45 28.06,37.41 27.29,37.41 | POT1. 9.22,73.19 10.31,74.28 TP63. | 58.89,14.12 58.89,15.22 58.25,15.86 50.63,15.86 50.62,15.87 C21.
  Top 0.61: v57.94,56.5 57.94,60.63 | 57.94,60.63 v55.4,60.63 | 57.73,65.07 63.22,65.07 65.56,65.07 65.56,65.09 | 57.73,65.07 57.62,65.07 57.73,65.19 | 57.73,65.07 57.73,63.92 57.62,63.8 57.73,63.8 57.73,62.65 57.62,62.53 57.73,62.53 57.94,62.53 57.94,60.63 | 40.17,13.96 40.17,14.6 46.85,21.29 SW1. 49.99,22.83 v51.27,24.12 | v40.16,8.24 40.17,13.96 | 13.5,39.04 v13.5,40.94 v13.49,40.94 11.7,40.94 C25. 5.87,40.94 5.23,41.58 5.23,45.7 5.87,46.34 C24. 6.83,48.87 v6.82,48.88 | C1. 26.82,32.05 C1. C2. | C10. 63.34,34.27 C10. | C10. C11. 63.34,36.18 63.32,36.19 C12. 63.32,39.34 v63.34,39.35 | C10. 63.34,34.29 v63.34,27.61 | LED1. 35.03,13.27 35.08,13.32 LED3. 37.57,13.27 37.62,13.32 LED4. 40.11,13.27 40.16,13.32 40.16,13.96 40.17,13.96
  Top 0.813: v83.66,22.21 R9. | DSP1. 51.27,64.76 v55.4,60.63 | v57.94,52.69 59.54,52.69 | LED2. 83.34,19.99 83.66,19.67
  Top 1.016: v83.66,22.21 83.66,19.67 81.75,17.77 C15. TP67. TP68. | 49.37,11.1 C21. | 49.37,11.1 49.37,11.01 | 50.86,9.51 49.37,9.51 49.37,11.1
  Top 1.27: C17. 95.08,26.66 v95.08,25.39 95.14,25.33 95.14,25.19
  Top 1.676: 95.14,25.19 95.14,32.95 C14.
  Bottom 0.305: 24.92,13.74 24.92,12.68 22.62,10.38 22.62,8.32 22.59,8.22 22.59,6.97 | v21.11,17.77 21.11,13.74 21.11,12.68 19.84,11.41 18.25,11.41 16.03,9.19 16.03,3.16 16.03,2.84 16.66,2.52 17.93,2.54 17.93,2.52 17.95,2.54 19.84,2.54 | 25.23,2.54 27.45,2.54 27.46,2.52 | v22.38,17.77 23.65,17.77 23.65,19.89 v23.65,21.57 | 19.84,19.89 v19.84,17.77 19.82,17.75 19.53,17.75 18.88,18.4 C28. | v30.95,41.26 29.36,41.26 29.36,41.59 | 30.63,3.17 28.11,3.17 28.09,3.16 | v27.46,21.57 27.46,19.89 | v13.49,33.96 15.39,32.05 v19.84,32.05 | 54.76,21.89 R25. 55.08,21.89 55.08,23.91
  Bottom 0.406: JP5. 13.17,58.09 12.54,58.09 | 48.73,52.69 55.28,52.69 | 55.08,25.39 55.07,25.4 R22. 53.17,25.39 R22. C9. | v28.09,32.05 28.09,22.21 v27.46,21.57 | 57.63,45.39 57.62,45.39 57.51,45.27 57.51,43.16
  Bottom 0.61: 87.9,22.85 87.9,22.41 88.1,22.21 | 55.28,50.15 55.28,51.31 55.4,51.42 55.28,51.42 55.28,52.58 55.4,52.69 55.28,52.69 v57.94,52.69 v57.94,56.5 | 55.28,59.04 55.4,59.04 v55.4,60.63 | 91.71,44.43 91.91,44.43 91.71,44.23 91.71,43.16 | 9.36,58.09 12.54,58.09 | 9.36,50.15 9.36,52.69 | 9.36,50.15 7.46,50.15 6.81,49.5 6.81,47.99 6.81,47.94 6.82,47.93 v6.82,48.88 | 91.71,43.16 91.59,43.16 91.58,43.15 | v13.49,40.94 13.49,42.53 14.76,43.8 R18. | 91.71,43.16 91.71,39.67 91.91,39.67 | 67.26,38.09 67.26,39.24 67.14,39.35 | 57.51,43.16 57.3,43.16 57.51,42.96 57.51,41.89 57.62,41.89 57.51,41.78 57.51,40.62 57.3,40.62 57.51,40.42 57.51,39.35 v63.34,39.35 67.14,39.35 | 67.14,39.35 67.26,39.35 | 55.08,23.91 55.08,25.39 57,27.3 C30. 63.03,27.3 v63.34,27.61 | TP30. TP25. 6.82,22.85 6.18,22.21 6.18,15.86 6.82,15.22 TP32. 8.09,8.24 10.95,5.38 12.85,5.38 15.08,3.16 16.03,3.16 | v51.27,24.12 C9. | 9.36,50.15 11.27,50.15
  Bottom 0.813: DSP1. 51.27,73.33 52.22,74.28 TP48. | 13.17,66.66 13.17,67.61 10.63,70.15 10.63,73.33 11.58,74.28 TP63. | 13.17,66.66 13.17,64.42 | 13.17,66.66 12.22,66.66 9.36,63.8 9.36,58.09 9.36,52.69 | 94.45,52.69 91.91,52.69 89.37,52.69 86.83,52.69 86.83,54.91 84.92,56.82 82.37,56.82
  Bottom 1.016: v83.66,22.21 88.1,22.21 | C16. 80.78,12.35 81.75,13.32 C15. | TP48. TP47. TP46. TP45. TP44. TP43. TP42. TP41. TP55. TP56. TP57. TP58. | TP63. TP64. | 49.37,3.16 74.13,3.16 | 74.13,3.16 TP68. | BAT1. 70.95,21.89 74.13,18.72 74.13,3.16 | 22.59,6.97 25.34,6.97 28.08,6.97 | 28.08,6.97 28.09,6.97 | 28.08,6.97 28.08,3.16 28.09,3.16 | 28.09,3.16 40.16,3.16 | 40.16,3.16 49.37,3.16 | 40.16,3.16 v40.16,8.24 | C14. 95.08,33.64 96.36,34.91 96.36,39.67 | TP59. TP60. | TP58. TP59. | 96.36,52.69 94.45,52.69 | TP58. TP59. | TP59. TP60. | TP60. 92.55,74.28 96.36,70.47 96.36,52.69 | 96.36,52.69 96.36,39.67 | 49.37,3.16 49.37,7.92 | 16.03,3.16 16.66,2.52 17.93,2.52 27.46,2.52 28.09,3.16 | 96.36,39.67 91.91,39.67 91.9,39.67 | 49.37,7.92 49.37,8.01 | 50.86,9.51 49.37,9.51 49.37,7.92
  other vias: 95.08,31.1 95.08,29.2 95.08,27.29 95.08,23.48
  pour Bottom (isolate 0.356, no thermals): 93.81,35.54 96.36,35.54 96.99,34.91 96.99,22.21 96.36,21.57 87.47,21.57 87.15,21.89 87.15,23.16 89.05,23.16 89.37,23.48 91.28,25.7 91.28,31.1 93.18,33 93.18,34.91
INTRTC  (via drill 0.61 pad 1.02)
  Top 0.305: v22.7,26.66 v43.33,26.66
  Bottom 0.305: R3. 66.81,45.72 65.56,46.97 51.59,46.97 50.32,45.7 50.32,33.64 v43.33,26.66 | 3.96,27.93 3.96,30.46 3.01,31.42 3.01,33 3.64,33.64 12.22,33.64 19.2,26.66 v22.7,26.66
  Bottom 0.61: R3. 81.95,45.7
INTXIO  (via drill 0.61 pad 1.02)
  Top 0.305: v3.96,15.22 3.96,11.1 10.31,4.75 12.85,4.75 16.03,1.57 32.22,1.57 35.39,4.75 61.75,4.75 72.22,15.22 72.22,35.23 69.69,37.77 69.69,53.32 69.05,53.96 v66.83,53.96
  Top 0.61: R2. v66.83,53.96
  Bottom 0.305: v3.96,15.22 3.96,24.12 | v66.83,53.96 65.04,53.96
  Bottom 0.61: v66.83,53.96 65.04,53.96
LCDRW  (via drill 0.61 pad 1.02)
  Top 0.305: v10.63,56.18 9.04,56.18 2.38,49.52 2.38,25.7 3.96,24.12 13.49,24.12 v14.76,25.39
  Bottom 0.305: v10.63,56.18 13.17,56.18 | v14.76,25.39 14.76,24.12
LED0  (via drill 0.61 pad 1.02)
  Top 0.305: 24.89,48.91 24.89,50.17 24.28,50.78 5.87,50.78 4.28,49.2 v4.28,32.37
  Bottom 0.305: v4.28,32.37 12.54,32.37 21.11,23.8 21.11,19.89
LED+
  Top 0.61: 51.91,52.37 50,52.37 48.73,51.1 48.73,48.56
MISO  (via drill 0.61 pad 1.02)
  Top 0.305: 22.34,46.36 24.57,46.36 v26.19,44.75 | 24.92,13.74 v24.92,15.54
  Bottom 0.305: v26.19,44.75 27.14,43.8 27.14,40.62 28.09,39.67 30.31,39.67 31.27,38.72 31.27,19.67 31.9,19.04 31.9,16.81 30.63,15.54 v24.92,15.54
MOSI  (via drill 0.61 pad 1.02)
  Top 0.305: 22.34,47.16 25.36,47.16 v27.77,44.75 | v32.22,31.1 31.9,30.78 22.7,30.78 14.44,22.53 v13.81,22.53 | IC10. 15.29,13.74 v13.81,15.22
  Bottom 0.305: v27.77,44.75 27.77,40.94 28.41,40.31 30.63,40.31 32.22,38.72 v32.22,31.1 | v13.81,15.22 v13.81,22.53
N$1
  Top 0.406: 7.77,71.74 7.77,74.28 9.36,75.87 16.98,75.87 18.25,74.6 18.25,66.66
N$2
  Top 0.406: T1. 59.5,49.17
  Top 0.61: T2. 59.5,49.17 59.52,49.2 | T1. 55.97,50.21 54.76,51.42 51.91,51.42
N$3
  Bottom 0.61: R20. 48.73,59.67 49.05,59.99 49.05,64.44 48.73,64.76 48.73,66.66
N$4  (via drill 0.61 pad 1.02)
  Top 0.305: 25.69,37.41 25.69,36 v24.92,35.23
  Top 0.61: 24.92,33.95 v24.92,35.23
  Bottom 0.61: v24.92,35.23 23.65,36.5 23.65,37.77 23.71,37.83 23.77,37.83
N$5  (via drill 0.61 pad 1.02)
  Top 0.305: 26.49,37.41 26.49,35.56 v26.82,35.23
  Top 0.61: 26.82,33.95 v26.82,35.23
  Bottom 0.61: v26.82,35.23 28.09,36.5 28.09,37.77 28.03,37.83 27.97,37.83
N$6  (via drill 0.61 pad 1.02)
  Top 0.61: v88.42,49.2 89.7,49.2
  Bottom 0.305: 86.83,46.97 86.83,46.95 86.86,46.95 | D1. 86.83,37.7
  Bottom 0.406: 86.83,37.7 86.83,46.97
  Bottom 0.61: IC7. 86.83,46.97 86.86,46.95 86.86,48.27 87.78,49.2 v88.42,49.2
N$7
  Bottom 0.406: 65.04,55.23 67.78,55.23 69.69,57.13 69.69,69.84 TP40.
N$8
  Bottom 0.406: 65.04,56.5 67.14,56.5 68.41,57.77 68.41,71.11 TP39.
N$9
  Bottom 0.406: TP38. 67.14,71.11 67.14,58.4 66.51,57.77 65.04,57.77
N$10
  Bottom 0.406: 65.04,59.04 65.04,70.67 TP37.
N$11
  Bottom 0.406: 55.28,57.77 57.62,57.77 58.89,59.04 58.89,69.2 TP36.
N$12
  Bottom 0.406: TP35. 56.98,69.84 56.98,65.39 53.17,61.58 53.17,57.13 53.81,56.5 55.28,56.5
N$13
  Bottom 0.406: TP34. 55.08,70.47 55.08,65.39 51.91,62.21 51.91,56.5 53.17,55.23 55.28,55.23
N$14
  Bottom 0.406: TP33. 53.81,66.03 50.63,62.85 50.63,55.86 52.54,53.96 55.28,53.96
N$15
  pour Bottom (isolate 0.356): 3.01,64.12 6.18,64.12 6.82,63.48 6.82,52.05 6.18,51.42 3.01,51.42 2.38,52.05 2.38,63.48
N$23  (via drill 0.61 pad 1.02)
  Top 0.406: 93.18,47.29 95.4,47.29 | v93.18,46.97 93.18,47.29 | C13. 92.86,49.2 93.18,48.88 93.18,47.29
  Bottom 0.406: 91.71,46.97 v93.18,46.97
N$24
  Bottom 0.61: 87.9,25.39 89.37,25.39 89.69,25.7 89.69,28.56 88.42,29.83
  Bottom 1.778: 88.54,29.83 88.42,29.83 81.75,29.83 L1.
N$25  (via drill 0.61 pad 1.02)
  Top 0.61: 86.19,26.66 v86.19,24.12
  Top 1.27: 89.7,26.66 86.19,26.66 86.19,25.39 86.14,25.33 L2.
  Top 1.676: L2. 86.14,31.05 88.73,33.64 90.64,33.64
  Bottom 0.61: v86.19,24.12 87.9,24.12
N$26
  Bottom 0.305: 22.38,13.74 22.38,12.68 19.84,10.14 19.85,8.54 19.85,6.97 19.85,4.12 19.84,4.11 R10.
N$27  (via drill 0.61 pad 1.02)
  Top 0.305: v24.92,22.85 29.68,22.85 32.54,19.99 32.54,18.71
  Bottom 0.305: 22.38,19.89 22.38,22.21 23.01,22.85 v24.92,22.85
N$28
  Top 1.27: 95.08,15.22 C18.
  Top 1.676: 95.14,16.69 95.08,16.69 95.08,15.22 95.08,12.68 93.18,10.78 KL1.
N$29
  Top 1.27: 86.19,15.22 89.7,15.22
  Top 1.676: 86.14,16.69 86.19,16.69 86.19,15.22 86.19,12.68 88.1,10.78 88.1,9.51
N$30  (via drill 0.61 pad 1.02)
  Top 0.813: 83.66,26.01 82.39,26.01 v82.39,26.02 82.37,26.01 R8.
  Bottom 0.61: 87.9,26.66 85.88,26.66 85.24,26.02 v82.39,26.02
N$31
  Top 0.406: 76.67,52.69 75.4,53.96 75.4,67.93 TP54.
N$32
  Top 0.406: 84.29,52.69 80.48,56.5 80.48,67.93 TP53.
N$33
  Top 0.406: 81.75,52.69 77.94,56.5 77.94,67.93 TP52.
N$34
  Top 0.406: 81.75,60.31 81.75,62.21 86.83,67.3 TP51.
N$35
  Top 0.406: 86.83,60.31 86.83,62.21 91.91,67.3 TP50.
N$36
  Top 0.406: 84.29,60.31 84.29,62.21 89.37,67.3 TP49.
N$37
  Top 0.305: 23.65,13.74 23.65,12.68 21.22,10.26 21.22,9.51
N$38  (via drill 0.61 pad 1.02)
  Top 0.305: v23.96,4.43 23.96,9.51
  Bottom 0.305: 26.19,13.74 26.19,12.68 23.96,10.46 23.96,9.51 | R12. v23.96,4.43
N$40
  Top 0.61: 35.08,15.27 R16.
N$41  (via drill 0.61 pad 1.02)
  Top 0.305: v26.82,23.8 30.95,23.8 35.08,19.67 35.08,18.71
  Bottom 0.305: 26.19,19.89 26.19,23.48 26.5,23.8 v26.82,23.8
N$42
  Top 0.305: 21.11,13.74 21.11,12.68 18.48,10.06 18.48,9.51
  Bottom 0.305: 18.48,9.51 18.48,8.47 17.93,7.92 R11.
N$43
  Top 0.406: 56.35,9.51 56.35,14.12
N$44
  Top 0.406: 57.62,14.27 57.62,14.12 57.62,10.98 59.09,9.51
N$45
  Top 0.61: 7.77,43.48 8.73,43.48 10,42.21 11.7,42.21
N$46  (via drill 0.61 pad 1.02)
  Top 0.305: v30.63,12.68 v30.63,17.77
  Bottom 0.305: 24.92,19.89 24.92,18.4 25.55,17.77 v30.63,17.77 | R13. 30.63,6.33 27.46,9.51 | 27.46,9.51 26.71,9.51 | 27.46,9.51 v30.63,12.68
N$47
  Top 0.305: 24.92,19.89 24.92,18.4 25.87,17.45 28.73,17.45 29.45,16.72 29.45,9.51
N$48
  Top 0.61: 32.54,15.27 R14.
N$49
  Top 0.813: R15. 78.53,22.16 78.53,19.99
N$50
  Top 0.406: 56.66,21.89 56.67,21.89 56.35,21.57 56.35,19.63
N$51
  Top 0.406: C20. 54.76,21.89 55.08,21.57 55.08,19.63
N$52
  Top 0.406: 60.15,21.89 60.16,21.89 60.16,19.63
N$53
  Top 0.406: 57.62,19.63 57.62,20.62 58.25,21.26 58.25,21.89 C19.
N$54  (via drill 0.61 pad 1.02)
  Top 0.305: v24.92,24.75 38.57,24.75 40.48,22.85 42.38,22.85 42.37,22.83 42.35,22.83
  Top 0.61: v9.68,44.75 9.68,44.43 10.63,43.48 11.7,43.48
  Bottom 0.305: v9.68,44.75 9.68,41.89 13.49,38.09 18.57,38.09 24.92,31.73 v24.92,24.75
  Bottom 0.61: 8.73,46.02 R19. | 8.73,46.02 8.73,45.7 v9.68,44.75 | T3. 8.66,45.96 8.73,46.02
N$55
  Top 0.61: R17. 17.3,37.13 17.18,37.25 IC12.
N$57
  Top 0.305: TP29. 9.36,21.57 14.44,21.57 22.7,29.83 37.3,29.83 45.55,38.09 56.05,38.09
N$58
  Top 0.305: TP28. 14.12,20.3 22.7,28.88 37.62,28.88 44.92,36.18 56.05,36.18
N$59
  Top 0.305: TP27. 9.36,19.04 13.81,19.04 22.7,27.93 37.94,27.93 44.28,34.27 56.05,34.27
N$60  (via drill 0.61 pad 1.02)
  Top 0.305: TP26. 13.49,17.77 21.42,25.7 47.78,25.7 v48.09,25.39
  Bottom 0.305: 49.37,25.4 49.37,25.39 v48.09,25.39
N$61  (via drill 0.61 pad 1.02)
  Top 0.305: 22.34,39.16 22.34,35.83 13.81,27.29 v13.81,26.34
  Bottom 0.305: 13.81,24.12 v13.81,26.34
N$62
  Bottom 0.406: TP24. 11.9,24.12 JP4.
N$63
  Top 0.61: 8.71,46.34 10.95,46.34 11.58,45.7 11.58,44.75 11.7,44.75
N$64  (via drill 0.61 pad 1.02)
  Top 0.305: 22.34,39.96 20.77,39.96 20.47,39.67 20.47,35.23 14.76,29.51 v13.81,29.51
  Bottom 0.305: 13.81,27.93 v13.81,29.51
N$65
  Bottom 0.406: TP23. JP3.
N$66  (via drill 0.61 pad 1.02)
  Top 0.305: 22.34,40.77 20.29,40.77 19.52,39.99 19.52,35.54 16.03,32.05 6.82,32.05 4.92,30.15 v4.92,29.51
  Bottom 0.305: 4.92,27.93 v4.92,29.51
N$67  (via drill 0.61 pad 1.02)
  Top 0.305: 22.34,41.56 19.82,41.56 18.57,40.31 18.57,35.86 15.71,33 6.5,33 3.64,30.15 3.64,26.97 v4.92,25.7
  Bottom 0.305: 4.92,24.12 v4.92,25.7
N$68
  Bottom 0.406: JP2. TP22.
N$69
  Bottom 0.406: JP1. 6.82,24.12 TP21.
N$70  (via drill 0.61 pad 1.02)
  Top 0.61: v23.33,59.99 23.33,66.66
  Bottom 0.61: 13.17,57.13 20.47,57.13 v23.33,59.99
N$71
  Bottom 0.406: 55.73,32.05 55.71,31.73 55.71,31.1 56.35,30.46 56.35,29.4 56.35,28.56 55.08,27.29 53.17,27.29 53.17,27.28
N$72  (via drill 0.61 pad 1.02)
  Top 0.305: 33.84,43.96 37.46,43.96 v43.97,50.47
  Bottom 0.305: v43.97,50.47 47.14,53.64 48.73,53.64
N$73  (via drill 0.61 pad 1.02)
  Top 0.406: 95.4,45.39 93.18,45.39 v93.18,45.7
  Bottom 0.406: 91.71,45.7 v93.18,45.7
N$74
  Bottom 0.406: T4. 16.95,52.66 BUZ1.
N$75  (via drill 0.61 pad 1.02)
  Top 0.305: v33.81,5.07 30.95,2.21 16.66,2.21 13.17,5.7 10.63,5.7 8.09,8.24 8.09,12.68 TP31.
  Bottom 0.305: v33.81,5.07 33.81,10.14 34.76,11.1 55.71,11.1 58.89,14.27 58.89,23.8
  Bottom 0.61: 58.89,23.91 58.89,23.8 58.78,23.91 57.62,23.91
N$77  (via drill 0.61 pad 1.02)
  Top 0.406: v51.91,45.39 JP6. | 37.62,18.71 37.62,18.72 v40.48,18.72
  Bottom 0.406: v51.91,45.39 51.91,33.64 45.55,27.29 45.55,23.8 v40.48,18.72
N$78
  Top 0.61: 37.62,15.27 R24.
N$79
  Bottom 0.406: 51.27,27.29 51.27,28.56 51.91,29.2 55.08,29.2 IC13. 55.08,29.51 | 51.27,27.29 51.27,27.28 | R7. 51.26,27.28 51.27,27.29
PROG  (via drill 0.61 pad 1.02)
  Top 0.305: v23.65,15.54 19.2,15.54 18.57,14.91 16.34,14.91 14.76,16.5 v2.38,16.5
  Bottom 0.305: 4.88,47.99 3.71,47.99 2.38,46.66 v2.38,16.5 | v23.65,15.54 23.65,13.74
PSEN  (via drill 0.61 pad 1.02)
  Top 0.305: v25.87,63.17 25.87,59.99 v27.77,58.09 | 33.84,41.56 35.7,41.56 36.03,41.58 36.98,42.53 v36.98,42.85
  Bottom 0.305: TP20. 27.14,73.01 27.14,64.44 v25.87,63.17 | v36.98,42.85 36.98,48.88 v27.77,58.09
RSTO  (via drill 0.61 pad 1.02)
  Top 0.305: 26.19,19.89 26.19,18.4 26.5,18.08 28.73,18.08 29.36,18.72 v29.36,21.57
  Top 0.406: 16.98,42.21 17.18,42.21 v18.57,42.21 19.52,43.16 19.52,44.12 20.15,44.75 22.34,44.75 22.34,44.77
  Bottom 0.305: v29.36,21.57 29.36,32.69 28.73,33.32 24.6,33.32 18.57,39.35 v18.57,42.21
  Bottom 0.61: 17.92,43.8 17.93,42.53 18.25,42.21 v18.57,42.21
RXD  (via drill 0.61 pad 1.02)
  Top 0.305: 22.34,43.96 23.48,43.96 23.96,43.48 v31.9,43.48 | v44.6,30.46 50,30.46 53.17,27.29 v53.17,21.89 | v55.08,12.68 55.08,14.12
  Bottom 0.305: v31.9,43.48 33.49,41.89 33.49,34.27 37.3,30.46 v44.6,30.46 | v53.17,21.89 53.17,17.77 55.08,15.86 v55.08,12.68
SCK  (via drill 0.61 pad 1.02)
  Top 0.305: 22.33,45.56 23.79,45.56 v24.6,44.75 | v30.31,32.05 32.85,32.05 v33.81,31.1
  Bottom 0.305: v24.6,44.75 26.5,42.85 26.5,36.5 25.87,35.86 25.87,34.59 26.5,33.96 29.04,33.96 30.31,32.69 v30.31,32.05 | IC11. 28.19,13.74 28.73,14.27 30.95,14.27 33.81,17.13 v33.81,31.1
SCL  (via drill 0.61 pad 1.02)
  Top 0.305: TP61. 14.44,70.47 R26. | R26. | R26. 14.44,59.99 21.11,53.32 25.55,53.32 v26.19,52.69 26.49,52.38 26.49,48.91 | v49.05,41.89 v63.97,41.89
  Top 0.406: v70.95,63.8 63.22,63.8 | v70.95,52.69 v70.95,44.43 v70.95,41.89
  Bottom 0.305: v26.19,52.69 29.04,52.69 34.12,47.61 34.12,34.59 37.62,31.1 39.84,31.1 42.38,33.64 42.38,35.23 v49.05,41.89 | v63.97,41.89 67.26,41.89
  Bottom 0.406: 94.45,60.31 94.45,60.95 91.59,63.8 v70.95,63.8 v70.95,52.69 65.04,52.69 64.92,52.69 | v70.95,44.43 81.95,44.43 | 67.26,41.89 v70.95,41.89
SDA  (via drill 0.61 pad 1.02)
  Top 0.305: TP62. 16.98,70.47 R27. | R27. | R27. 16.98,60.63 23.33,54.28 26.82,54.28 v27.46,53.64 27.46,51.1 27.29,50.94 27.29,48.91 | v48.73,43.16 v63.97,43.16
  Top 0.406: v72.22,62.53 IC2. | v72.22,43.16 v72.22,51.42
  Bottom 0.305: v27.46,53.64 29.36,53.64 34.76,48.24 34.76,34.91 37.94,31.73 39.2,31.73 41.43,33.96 41.43,35.86 v48.73,43.16 | v63.97,43.16 67.26,43.16
  Bottom 0.406: 91.91,60.31 91.28,61.26 90,62.53 v72.22,62.53 v72.22,51.42 65.04,51.42 64.92,51.42 | 81.95,43.16 v72.22,43.16 67.26,43.16
TXD  (via drill 0.61 pad 1.02)
  Top 0.305: 22.34,42.36 23.8,42.36 23.96,42.53 v30.95,42.53 | v43.33,29.51 50,29.51 52.54,26.97 52.54,22.53 v51.91,21.89 | 53.81,14.27 53.81,14.12 v53.81,12.68
  Bottom 0.305: v30.95,42.53 31.27,42.53 32.85,40.94 32.85,33.96 37.3,29.51 v43.33,29.51 | v51.91,21.89 51.91,17.77 53.81,15.86 v53.81,12.68
UBATT
  Bottom 0.61: BAT1.TT 73.02,31.89 80.86,39.74 85.84,39.74
V+
  Top 0.406: C22. 59.54,17.75 58.89,18.4 58.89,19.63
V-
  Top 0.406: 49.37,17.75 53.16,17.75 53.81,18.4 53.81,19.63 53.81,19.67

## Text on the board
Top: JP6 | TOP | Uin | GND
Bottom: JP7 | JP5 | JP8 | JP2 | JP3 | JP1 | JP4 | BOT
